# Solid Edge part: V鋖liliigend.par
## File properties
Author: Türk
Template: Iso Part.par
Last saved by: Türk
Revision: 2
Application: Solid Edge
Accuracy: 0,990
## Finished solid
Body 1: solid body, 8 faces, 8 edges, 2 vertices.
  Faces by surface: cylinder 4, plane 4
  Edges by curve: circle 4, ellipse 4
Bounding box of the edges (mm): 55.000 x 55.000 x 15.000, from (-27.5, -27.5, -7.5) to (27.5, 27.5, 7.5).
Cylindrical faces by radius (mm): R7.5 x4
Planar faces by outward normal: +x 1, +y 1, -x 1, -y 1
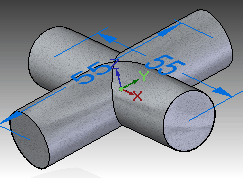
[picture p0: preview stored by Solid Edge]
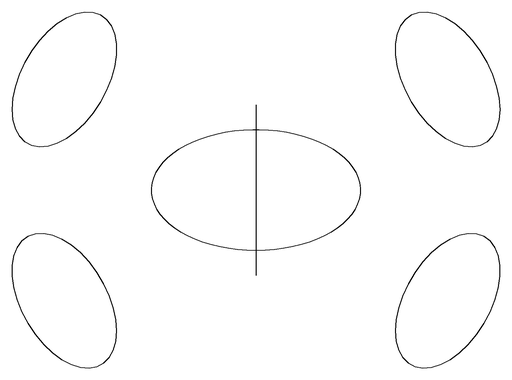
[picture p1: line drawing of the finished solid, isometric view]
